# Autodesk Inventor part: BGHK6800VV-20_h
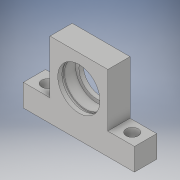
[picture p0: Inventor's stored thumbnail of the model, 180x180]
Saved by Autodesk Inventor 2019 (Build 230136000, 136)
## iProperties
Created: 2022-11
Part Number: BGHK6800VV-20_h
Material: Generic
Catalog Web Link: www.cadenas.de
Description: BGHKB, BGHK, BGHKA, BGHKSA, BGHKS_housing-Bearings with Housings - T-Shaped - h Selectable
Vendor: MISUMI
Document SubType Name: Modeling
Designer: psAdmin
Manufacturer: MISUMI
Mass: 8.05926 g
Surface Area: 44.1935 cm^2
Volume: 8.05926 cm^3
Density: 1 g/cm^3
Appearance: PSOLRGB-175-175-175
Category: PARTsolutions
Company: MISUMI
Title: BGHK6800VV-20
Author: Cadenas PARTsolutions
Comments: Bearings with Housings - T-Shaped - h Selectable
PSOL_IDENT_0: {$CADENAS_DATA/23d-libs/misumi/metric/12_bearing_holders/bghkb/bghkb_housing.prj},237 {VTYP=3D},{NB=
PSOL_IDENT_1: BGHK6800VV-20_h},{LINA=BGHK6800VV-20},{NN=BGHKB, BGHK, BGHKA, BGHKSA, BGHKS_housing},{DATE=30.03.201
PSOL_IDENT_2: 8 01:48:21},{GEOMDATE=23.03.2015 00:00:00},{VERSION=},{LINEID=300},{WBVAR=MATB,MATH,STH,SEAL,HH,ALT1
PSOL_IDENT_3: ,ALT2},{WBNUMERIC=HH}  {NB=BGHK6800VV-20_h},{LINA=BGHK6800VV-20},{KT=DUMMY},{PN=BGHK6800VV-20},{TYPE=
PSOL_IDENT_4: BGHK},{MATB=S},{MATBALG='S','Steel','SS','Stainless Steel'},{MATH=S45C},{MATHALG='S45C','1045 Carbon
PSOL_IDENT_5: Steel','2017AA','2017 Aluminum Alloy'},{STH=ENP},{STHALG='BO','Black Oxide','ENP','Electroless Nick
PSOL_IDENT_6: el Plating'},{ARR=304 Stainless Steel},{ARR3D=-S},{BN=6800},{SEAL=VV},{SEALALG='ZZ','Double Shielded'
PSOL_IDENT_7: ,'VV','Non-Contact Sealed Rubber Seal','DD','Contact Sealed Rubber Seal'},{HH=20},{HHALG=[20,25,30]}
PSOL_IDENT_8: ,{DD=10},{D=19},{DD2=20},{MM=1.15},{DDHH=16},{B=5},{LL1=2},{H=34},{H2=14},{L=50},{L1=38.0},{L2=26},{
PSOL_IDENT_9: T=10},{S=10},{DD1=5.5},{ALT1=},{ALT2=}
NB: BGHK6800VV-20_h
NN: BGHKB, BGHK, BGHKA, BGHKSA, BGHKS_housing
NT: Bearings with Housings - T-Shaped - h Selectable
NBSYN: $PN._h
LINA: BGHK6800VV-20
CATALOG: Misumi
PN: BGHK6800VV-20
MATB: Steel
MATH: 1045 Carbon Steel
STH: Electroless Nickel Plating
ARR: 304 Stainless Steel
BN: 6800
SEAL: Non-Contact Sealed Rubber Seal
HH: 20
DD: 10
D: 19
DDHH: 16
B: 5
LL1: 2
H: 34
L: 50
L1: 38
L2: 26
T: 10
S: 10
DD1: 5.5
ALT1: Bearings, Retaining Rings Assembled
ALT2: w/o KCC (C2 Chamfer)
SUPPLIER: MISUMI
ARTICLENO: BGHK6800VV-20_h
BOMINFO: BGHK6800VV-20
CREATOR: CADENAS GmbH
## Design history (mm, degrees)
sketch "Sketch_1"
  geometry: L1 (-25, -10)-(-25, -20); L2 (-25, -20)-(25, -20); L3 (25, -20)-(25, -10); L4 (25, -10)-(13, -10); L5 (13, -10)-(13, 14); L6 (13, 14)-(-13, 14); L7 (-13, 14)-(-13, -10); L8 (-13, -10)-(-25, -10)
  constraints: 16 end point
extrude "Extrusion1" join sketch "Sketch_1" stored distance "d0" = 10; taper "d1" = 0 deg
sketch "Sketch2"
  geometry: 1 further point
hole "Hole1" sketch "Sketch2" at (0, 0) diameter "d2" = 16; stored, may be unused: countersink angle "d6" = 90 deg, drill point angle "d8" = 0 deg; dims "d3" = 6, "d4" = 19, "d5" = 8, "d7" = 10
sketch "Sketch3"
  geometry: 1 further point
hole "Hole2" sketch "Sketch3" at (6, -5) diameter "d9" = 5.5; stored, may be unused: countersink angle "d13" = 90 deg, drill point angle "d15" = 0 deg; dims "d10" = 6, "d11" = 4, "d12" = 2, "d14" = 10
sketch "Sketch4"
  geometry: 1 further point
hole "Hole3" sketch "Sketch4" at (44, -5) diameter "d16" = 5.5; stored, may be unused: countersink angle "d20" = 90 deg, drill point angle "d22" = 0 deg; dims "d17" = 6, "d18" = 4, "d19" = 2, "d21" = 10
sketch "Sketch_4"
  geometry: L1 (-2, 0)-(-3.15, 0); L2 (-3.15, 0)-(-3.15, 10); L3 (-3.15, 10)-(-2, 10); L4 (-2, 10)-(-2, 0); L5 (-2, 0)-(-3.15, 0)
  constraints: 10 end point
revolve "Revolution1" sketch "Sketch_4" stored, may be unused: angle "d23" = 360 deg
node "housing_to_dummy_XY"
node "housing_to_dummy_YZ"
node "housing_to_dummy_ZX"
node "housing_to_dummy_X"
node "housing_to_dummy_Y"
node "housing_to_dummy_Z"
node "housing_to_dummy_Center"
node "to_bearing_XY"
node "to_bearing_YZ"
node "to_bearing_ZX"
node "to_bearing_X"
node "to_bearing_Y"
node "to_bearing_Z"
node "to_bearing_Center"
node "to_rring_XY"
node "to_rring_YZ"
node "to_rring_ZX"
node "to_rring_X"
node "to_rring_Y"
node "to_rring_Z"
node "to_rring_Center"
body "Solid1"
other parameters: "d24" = 0, "d25" = 0
